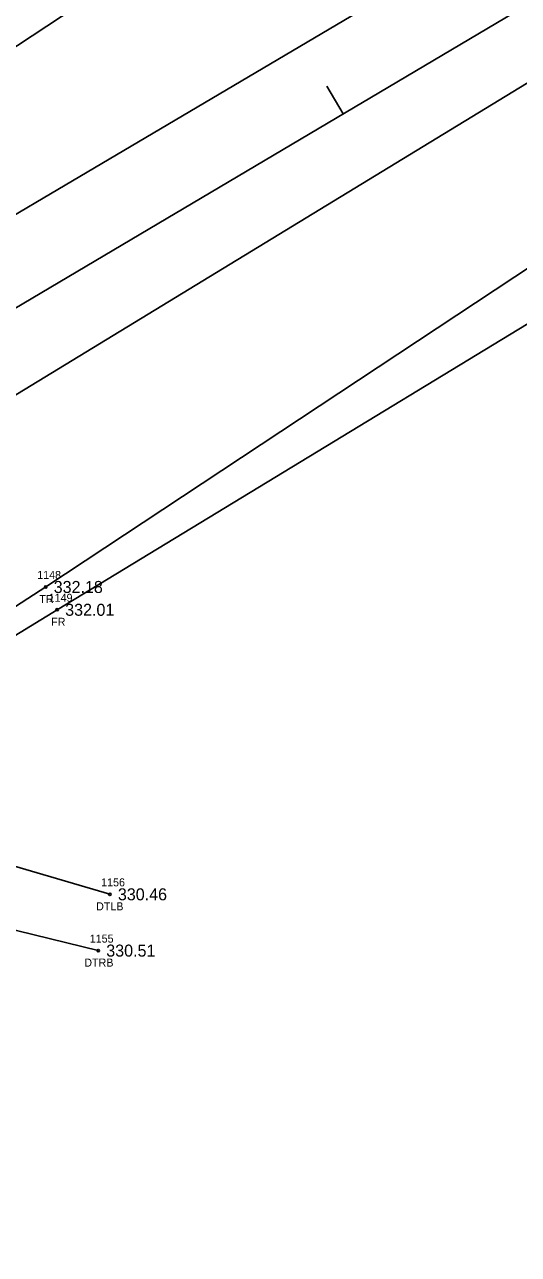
# Model space of a CAD drawing. Extents: x 2231119 to 2232595, y 1035731 to 1037094.
# Drawn here: x 2231785.8 to 2231847.5, y 1036450.5 to 1036604.1 of the extents above; entities that cross this region are included whole.
import ezdxf

# ---------------------------------------------------------------- set-up
doc = ezdxf.new("R2010")
doc.units = 0
for name, color, linetype in [('RD_EX_Fence_Other', 7, 'Continuous'), ('RD_EX_Fence_Other_txCode', 7, 'Continuous'), ('RD_EX_H2O', 7, 'Continuous'), ('RD_EX_H2O_txCode', 7, 'Continuous'), ('RD_EX_Road', 7, 'Continuous'), ('RD_EX_TX_Fence_Other_ELEV', 7, 'Continuous'), ('RD_EX_TX_H2O_ELEV', 7, 'Continuous'), ('RD_EX_TX_VEG_ELEV', 7, 'Continuous'), ('RD_EX_VEG', 7, 'Continuous'), ('RD_EX_VEG_txCode', 7, 'Continuous'), ('RD_HC_Cl', 7, 'Continuous'), ('RD_HC_Data_Tic', 7, 'Continuous'), ('RD_SMD_Locator', 7, 'Continuous')]:
    doc.layers.add(name, color=color, linetype=linetype)

msp = doc.modelspace()

# ---------------------------------------------------------------- linework, layer by layer
at = {"layer": 'RD_EX_Fence_Other'}
msp.add_lwpolyline([(2231742.82, 1036485.51), (2231730.99, 1036494.96), (2231789.88, 1036531.02), (2231876.81, 1036583.89), (2231964.37, 1036635.23), (2232046.18, 1036684.79), (2232133.57, 1036734.4), (2232210.6, 1036793.49), (2232301.78, 1036835.03)], dxfattribs=at)
at = {"layer": 'RD_EX_H2O'}
for points in [[(2231756.42, 1036502.66), (2231760.43, 1036506.07), (2231796.46, 1036495.47)], [(2231756.42, 1036502.66), (2231754.67, 1036498.34), (2231795.01, 1036488.44)]]:
    msp.add_lwpolyline(points, dxfattribs=at)
at = {"layer": 'RD_EX_Road'}
for points in [[(2231606.1, 1036462.92), (2231601.27, 1036470.82), (2231681.58, 1036519.84), (2231764.99, 1036568.78), (2231851.5, 1036619.95), (2231935.62, 1036669.65), (2232021.78, 1036720.22), (2232106.75, 1036770.57), (2232190.54, 1036819.2), (2232275.92, 1036870.27)], [(2231606.1, 1036462.92), (2231610.57, 1036455.36), (2231692.09, 1036503.24), (2231706.07, 1036512.59), (2231777.1, 1036553.27), (2231861.39, 1036604.65), (2231946.39, 1036654.77), (2232031.07, 1036704.2), (2232117.06, 1036755.16), (2232199.91, 1036803.8), (2232286.7, 1036855.36)]]:
    msp.add_lwpolyline(points, dxfattribs=at)
at = {"layer": 'RD_EX_VEG'}
for points in [[(2231598.25, 1036478.35), (2231674.54, 1036527.95), (2231759.25, 1036584.63), (2231839.99, 1036637.88), (2231924.53, 1036692.24), (2232004.98, 1036742.14), (2232090.99, 1036793.16), (2232172.16, 1036843), (2232262.27, 1036890.61)], [(2231753.59, 1036474.98), (2231730.55, 1036496.34), (2231788.45, 1036533.87), (2231871.45, 1036588.79), (2231958.94, 1036639.51), (2232040.64, 1036687.92), (2232130.59, 1036740.48), (2232213.07, 1036784.39), (2232299.54, 1036835.55)]]:
    msp.add_lwpolyline(points, dxfattribs=at)
at = {"layer": 'RD_HC_Cl'}
msp.add_line((2231548.98, 1036428.87), (2232281.06, 1036863.23), dxfattribs=at)
at = {"layer": 'RD_HC_Data_Tic'}
msp.add_line((2231825.6, 1036593), (2231823.55, 1036596.44), dxfattribs=at)
at = {"layer": 'RD_SMD_Locator'}
for centre in [(2231788.45, 1036533.87), (2231789.88, 1036531.02), (2231796.46, 1036495.47), (2231795.01, 1036488.44)]:
    msp.add_circle(centre, 0.15, dxfattribs=at)

# ---------------------------------------------------------------- texts
at = {"layer": 'RD_EX_Fence_Other_txCode'}
for s, p in [('1149', (2231788.82, 1036532.02)), ('FR', (2231789.13, 1036529.02))]:
    msp.add_text(s, height=1, dxfattribs=at).set_placement(p)
at = {"layer": 'RD_EX_H2O_txCode'}
for s, p in [('1156', (2231795.37, 1036496.47)), ('DTLB', (2231794.74, 1036493.47)), ('1155', (2231793.95, 1036489.44)), ('DTRB', (2231793.27, 1036486.44))]:
    msp.add_text(s, height=1, dxfattribs=at).set_placement(p)
at = {"layer": 'RD_EX_TX_Fence_Other_ELEV'}
msp.add_text('332.01', height=1.5, dxfattribs=at).set_placement((2231790.88, 1036530.27))
at = {"layer": 'RD_EX_TX_H2O_ELEV'}
for s, p in [('330.46', (2231797.46, 1036494.72)), ('330.51', (2231796.01, 1036487.69))]:
    msp.add_text(s, height=1.5, dxfattribs=at).set_placement(p)
at = {"layer": 'RD_EX_TX_VEG_ELEV'}
msp.add_text('332.18', height=1.5, dxfattribs=at).set_placement((2231789.45, 1036533.12))
at = {"layer": 'RD_EX_VEG_txCode'}
for s, p in [('1148', (2231787.39, 1036534.87)), ('TR', (2231787.66, 1036531.87))]:
    msp.add_text(s, height=1, dxfattribs=at).set_placement(p)

doc.saveas('drawing.dxf')
